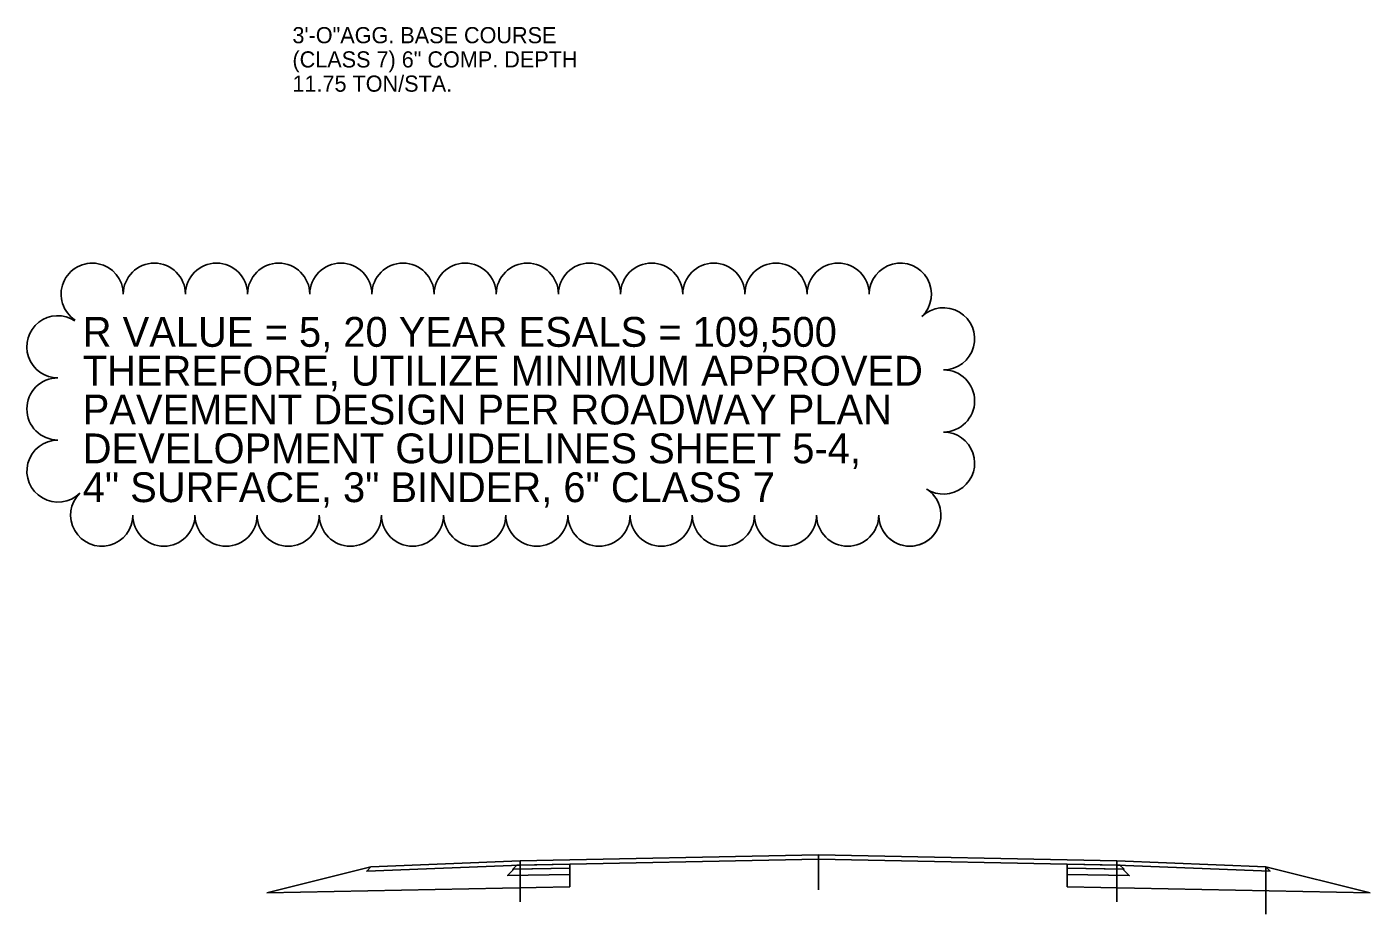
# Model space of a CAD drawing. Extents: x 1373719 to 1374161, y 379835 to 380167.
# Drawn here: x 1374055 to 1374109, y 380081.4 to 380117.1 of the extents above; entities that cross this region are included whole.
import ezdxf

# ---------------------------------------------------------------- set-up
doc = ezdxf.new("R2010")
doc.units = 0
for name, color, linetype in [('_30% NOTES', 7, 'Continuous'), ('Agg Base Course Text', 7, 'Continuous'), ('T_Drafting', 7, 'Continuous')]:
    doc.layers.add(name, color=color, linetype=linetype)

msp = doc.modelspace()

# ---------------------------------------------------------------- linework, layer by layer
at = {"layer": '_30% NOTES'}
for centre, start, end in [((1374057.589, 380106.338), 0, 236.9636), ((1374060.089, 380106.338), 0, 180), ((1374062.589, 380106.338), 0, 180), ((1374065.089, 380106.338), 0, 180), ((1374067.589, 380106.338), 0, 180), ((1374070.089, 380106.338), 0, 180), ((1374072.589, 380106.338), 0, 180), ((1374075.089, 380106.338), 0, 180), ((1374077.589, 380106.338), 0, 180), ((1374080.089, 380106.338), 0, 180), ((1374082.589, 380106.338), 0, 180), ((1374085.089, 380106.338), 0, 180), ((1374087.589, 380106.338), 0, 180), ((1374090.089, 380106.338), 314.1183, 180), ((1374091.829, 380104.543), 270, 134.1183), ((1374056.212, 380104.221), 56.9636, 270), ((1374091.829, 380102.043), 270, 90), ((1374056.212, 380101.721), 90, 270), ((1374056.212, 380099.221), 90, 314.8317), ((1374091.829, 380099.543), 237.0496, 90), ((1374057.973, 380097.45), 134.8317, 0), ((1374090.473, 380097.45), 180, 57.0496), ((1374060.473, 380097.45), 180, 0), ((1374062.973, 380097.45), 180, 0), ((1374065.473, 380097.45), 180, 0), ((1374067.973, 380097.45), 180, 0), ((1374070.473, 380097.45), 180, 0), ((1374072.973, 380097.45), 180, 0), ((1374075.473, 380097.45), 180, 0), ((1374077.973, 380097.45), 180, 0), ((1374080.473, 380097.45), 180, 0), ((1374082.973, 380097.45), 180, 0), ((1374085.473, 380097.45), 180, 0), ((1374087.973, 380097.45), 180, 0), ((1374087.973, 380097.45), 180, 0), ((1374090.473, 380097.45), 180, 0)]:
    msp.add_arc(centre, 1.25, start, end, dxfattribs=at)
at = {"layer": 'T_Drafting'}
for p, q in [((1374086.796, 380083.778), (1374086.796, 380082.377)), ((1374086.796, 380083.778), (1374086.796, 380082.377)), ((1374068.796, 380083.298), (1374064.608, 380082.251)), ((1374074.796, 380083.538), (1374074.796, 380081.886)), ((1374076.796, 380083.412), (1374076.798, 380082.495)), ((1374096.796, 380083.412), (1374096.795, 380082.495)), ((1374098.796, 380083.538), (1374098.796, 380081.886)), ((1374104.796, 380083.298), (1374108.985, 380082.251)), ((1374104.796, 380083.298), (1374104.796, 380081.396)), ((1374076.798, 380082.495), (1374064.608, 380082.251)), ((1374096.795, 380082.495), (1374108.985, 380082.251))]:
    msp.add_line(p, q, dxfattribs=at)
for points in [[(1374086.796, 380083.778), (1374074.796, 380083.538), (1374068.796, 380083.298), (1374068.63, 380083.132), (1374074.796, 380083.372), (1374086.796, 380083.612)], [(1374086.796, 380083.778), (1374098.796, 380083.538), (1374104.796, 380083.298), (1374104.963, 380083.132), (1374098.796, 380083.372), (1374086.796, 380083.612)], [(1374076.798, 380083.245), (1374074.548, 380083.2), (1374074.298, 380082.95), (1374076.798, 380082.995)], [(1374076.796, 380083.412), (1374074.671, 380083.369), (1374074.505, 380083.202), (1374076.798, 380083.245)], [(1374096.796, 380083.412), (1374098.921, 380083.369), (1374099.088, 380083.202), (1374096.795, 380083.245)], [(1374096.795, 380083.245), (1374099.045, 380083.2), (1374099.295, 380082.95), (1374096.795, 380082.995)]]:
    msp.add_lwpolyline(points, dxfattribs=at)

# ---------------------------------------------------------------- texts
at = {"layer": '_30% NOTES'}
for s, p in [('R VALUE = 5, 20 YEAR ESALS = 109,500', (1374057.209, 380104.221)), ('THEREFORE, UTILIZE MINIMUM APPROVED', (1374057.209, 380102.659)), ('PAVEMENT DESIGN PER ROADWAY PLAN', (1374057.209, 380101.097)), ('DEVELOPMENT GUIDELINES SHEET 5-4,', (1374057.209, 380099.534)), ('4" SURFACE, 3" BINDER, 6" CLASS 7', (1374057.209, 380097.972))]:
    msp.add_text(s, height=1.2, dxfattribs=at).set_placement(p)
at = {"layer": 'Agg Base Course Text'}
for s, p in [('3\'-O"AGG. BASE COURSE', (1374065.643, 380116.433)), ('(CLASS 7) 6" COMP. DEPTH', (1374065.643, 380115.458)), ('11.75 TON/STA.', (1374065.643, 380114.483))]:
    msp.add_text(s, height=0.65, dxfattribs=at).set_placement(p)

doc.saveas('drawing.dxf')
